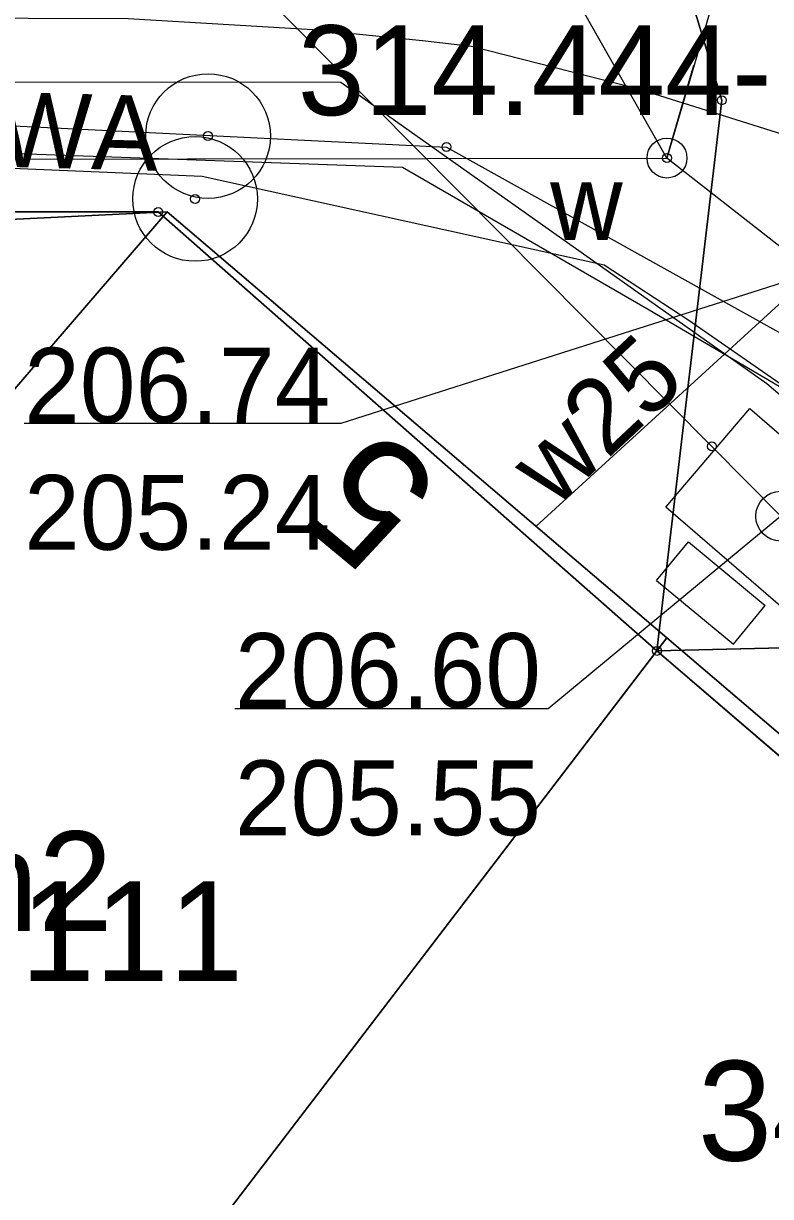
# Model space of a CAD drawing. Extents: x 6512400 to 6513200, y 6022500 to 6022750.
# Drawn here: x 6512795.61 to 6512803.1, y 6022664.87 to 6022676.63 of the extents above; entities that cross this region are included whole.
import ezdxf

# ---------------------------------------------------------------- set-up
doc = ezdxf.new("R2010")
doc.units = 0
for name, color, linetype in [('121-Punkt osnowy szczegółowej', 7, 'Continuous'), ('121-Punkt osnowy szczegółowej-Atr103', 7, 'Continuous'), ('203-punkt graniczny', 7, 'Continuous'), ('211-numer działki ewidencyjnej', 7, 'Continuous'), ('216-obręb ewidencyjny', 7, 'Continuous'), ('217-kontur klasyfikacyjny', 7, 'Continuous'), ('218-kontur użytku gruntowego', 7, 'Continuous'), ('219-działka ewidencyjna', 7, 'Continuous'), ('238-Punkt adresowy budynku', 7, 'Continuous'), ('312-budynek ewidencyjny', 7, 'Continuous'), ('312-oznaczenie budynku ewidencyjnego', 7, 'Continuous'), ('312-oznaczenie budynku ewidencyjnego-Atr117', 7, 'Continuous'), ('320-blok - kondygnacja nadziemna', 7, 'Continuous'), ('chodnik (powierzchnia)', 7, 'Continuous'), ('inna obudowa przewodu - sieć telekomunikacyjna (linia)', 7, 'Continuous'), ('inna obudowa przewodu - sieć wodociągowa (linia)', 7, 'Continuous'), ('komora podziemna - przewód telekomunikacyjny (powierzchnia)', 7, 'Continuous'), ('krawężnik (linia)', 7, 'Continuous'), ('przewód elektroenergetyczny (linia)', 7, 'Continuous'), ('przewód elektroenergetyczny (linia)-Atr1', 7, 'Continuous'), ('przewód telekomunikacyjny (linia)', 7, 'Continuous'), ('przewód wodociągowy (linia)', 7, 'Continuous'), ('przewód wodociągowy (linia)-Atr1', 7, 'Continuous'), ('punkt o określonej wysokości (sieć telekomunikacyjna)', 7, 'Continuous'), ('punkt o określonej wysokości (sieć telekomunikacyjna)-Atr2', 7, 'Continuous'), ('punkt o określonej wysokości (sieć telekomunikacyjna)-Atr3', 7, 'Continuous'), ('punkt o określonej wysokości (sieć wodociągowa)', 7, 'Continuous'), ('punkt o określonej wysokości (sieć wodociągowa)-Atr2', 7, 'Continuous'), ('punkt o określonej wysokości (sieć wodociągowa)-Atr3', 7, 'Continuous'), ('szafa telekomunikacyjna (punkt)', 7, 'Continuous'), ('właz okrągły - siec telekomunikacyjna (punkt)', 7, 'Continuous'), ('zasuwa - siec wodociągowa (punkt)', 7, 'Continuous'), ('zasuwa - siec wodociągowa (punkt)-Atr17', 7, 'Continuous')]:
    doc.layers.add(name, color=color, linetype=linetype)

# ---------------------------------------------------------------- blocks, each defined once
blk = doc.blocks.new('203')
blk.add_circle((0, 0), 0.045)
blk = doc.blocks.new('US17')
for p, q in [((-0.5, -0.25), (-0.5, 0.25)), ((-0.5, 0.25), (0.5, 0.25)), ((0.5, -0.25), (0.5, 0.25)), ((-0.5, -0.25), (0.5, -0.25))]:
    blk.add_line(p, q)
blk = doc.blocks.new('US22')
blk.add_circle((0, 0), 0.25)
blk = doc.blocks.new('PW01')
blk.add_circle((0, 0), 0.045)
blk = doc.blocks.new('US25')
blk.add_circle((0, 0), 0.2)
blk = doc.blocks.new('121')
for radius in [0.625, 0.045]:
    blk.add_circle((0, 0), radius)

msp = doc.modelspace()

# ---------------------------------------------------------------- linework, layer by layer
at = {"layer": '216-obręb ewidencyjny'}
for points in [[(6512688.62, 6022674.91), (6512702.58, 6022674.18), (6512725.78, 6022672.95), (6512730.35, 6022672.71), (6512735.76, 6022672.94), (6512745.51, 6022673.33), (6512754.87, 6022673.72), (6512768.24, 6022674.27), (6512785.56, 6022674.74), (6512790.49, 6022674.74), (6512796.96, 6022674.74), (6512801.96, 6022670.34), (6512828.67, 6022670.98), (6512833.61, 6022675.02), (6512836.69, 6022675.17), (6512851.94, 6022675.93)], [(6512836.687, 6022675.173), (6512833.61, 6022675.02), (6512828.67, 6022670.98), (6512801.96, 6022670.34), (6512810.18, 6022663.28), (6512825.37, 6022649.66), (6512838.47, 6022634.29), (6512852.25, 6022608.25), (6512853.17, 6022604.51), (6512855.78, 6022583.95), (6512858.85, 6022571.74), (6512828.23, 6022562.62), (6512818.47, 6022559.72), (6512824.714, 6022553.406)], [(6512780.7, 6022581.02), (6512806.2, 6022572.11), (6512806.62, 6022563.51), (6512811.41, 6022558.95), (6512818.47, 6022559.72), (6512828.23, 6022562.62), (6512858.85, 6022571.74), (6512855.78, 6022583.95), (6512853.17, 6022604.51), (6512852.25, 6022608.25), (6512838.47, 6022634.29), (6512825.37, 6022649.66), (6512810.18, 6022663.28), (6512801.96, 6022670.34), (6512796.96, 6022674.74), (6512790.49, 6022674.74), (6512785.56, 6022674.74), (6512768.24, 6022674.27)]]:
    msp.add_lwpolyline(points, dxfattribs=at)
at = {"layer": '217-kontur klasyfikacyjny'}
for points in [[(6512801.96, 6022670.34), (6512795.54, 6022661.95)], [(6512810.18, 6022663.28), (6512801.96, 6022670.34)]]:
    msp.add_lwpolyline(points, dxfattribs=at)
at = {"layer": '218-kontur użytku gruntowego'}
for points in [[(6512798.3, 6022690.12), (6512802.61, 6022675.86)], [(6512802.61, 6022675.86), (6512798.3, 6022690.12)], [(6512802.61, 6022675.86), (6512801.96, 6022670.34)], [(6512801.96, 6022670.34), (6512802.61, 6022675.86)], [(6512796.96, 6022674.74), (6512785.56, 6022674.74)], [(6512785.56, 6022674.74), (6512796.96, 6022674.74)], [(6512801.96, 6022670.34), (6512796.96, 6022674.74)], [(6512796.96, 6022674.74), (6512801.96, 6022670.34)], [(6512801.96, 6022670.34), (6512828.67, 6022670.98)], [(6512828.67, 6022670.98), (6512801.96, 6022670.34)], [(6512801.96, 6022670.34), (6512795.54, 6022661.95)], [(6512795.54, 6022661.95), (6512801.96, 6022670.34)], [(6512810.18, 6022663.28), (6512801.96, 6022670.34)], [(6512801.96, 6022670.34), (6512810.18, 6022663.28)]]:
    msp.add_lwpolyline(points, dxfattribs=at)
at = {"layer": '219-działka ewidencyjna'}
for points in [[(6512802.61, 6022675.86), (6512798.3, 6022690.12)], [(6512802.61, 6022675.86), (6512801.96, 6022670.34)], [(6512796.96, 6022674.74), (6512790.49, 6022674.74)], [(6512801.96, 6022670.34), (6512796.96, 6022674.74)], [(6512828.67, 6022670.98), (6512801.96, 6022670.34)], [(6512801.96, 6022670.34), (6512795.54, 6022661.95)], [(6512801.96, 6022670.34), (6512810.18, 6022663.28)]]:
    msp.add_lwpolyline(points, dxfattribs=at)
at = {"layer": '312-budynek ewidencyjny'}
for points in [[(6512785.32, 6022674.17), (6512797.05, 6022674.74)], [(6512789.92, 6022666.46), (6512797.05, 6022674.74)], [(6512797.05, 6022674.74), (6512789.92, 6022666.46)], [(6512797.05, 6022674.74), (6512802.06, 6022670.47)], [(6512795.54, 6022661.95), (6512802.06, 6022670.47)], [(6512802.06, 6022670.47), (6512795.54, 6022661.95)], [(6512802.06, 6022670.47), (6512810.3, 6022663.44)]]:
    msp.add_lwpolyline(points, dxfattribs=at)
at = {"layer": '320-blok - kondygnacja nadziemna'}
msp.add_lwpolyline([(6512789.92, 6022666.46), (6512797.05, 6022674.74), (6512785.32, 6022674.17), (6512786.09, 6022669.52)], close=True, dxfattribs=at)
at = {"layer": 'chodnik (powierzchnia)'}
for points in [[(6512768.21, 6022674.06), (6512768.55, 6022674.06), (6512785.32, 6022674.17), (6512797.05, 6022674.74)], [(6512845.61, 6022610.5), (6512844.69, 6022613.44), (6512844.06, 6022613.28), (6512843.41, 6022615.01), (6512844.01, 6022615.23), (6512838.87, 6022629.83), (6512839.52, 6022630.32), (6512838.94, 6022631.84), (6512838.15, 6022631.88), (6512837.86, 6022632.79), (6512838.13, 6022633.96), (6512826.89, 6022646.81), (6512825.11, 6022648.85), (6512824.32, 6022649.76), (6512820.29, 6022654.03), (6512817.62, 6022656.88), (6512816.1, 6022658.5), (6512810.3, 6022663.44), (6512802.06, 6022670.47), (6512797.05, 6022674.74)]]:
    msp.add_lwpolyline(points, dxfattribs=at)
at = {"layer": 'inna obudowa przewodu - sieć telekomunikacyjna (linia)'}
msp.add_lwpolyline([(6512802.54, 6022672.36), (6512802.51, 6022672.39), (6512787.26, 6022687.76), (6512787.22, 6022687.8)], dxfattribs=at)
at = {"layer": 'inna obudowa przewodu - sieć wodociągowa (linia)'}
msp.add_lwpolyline([(6512787.61, 6022675.99), (6512796.6, 6022675.55)], dxfattribs=at)
at = {"layer": 'komora podziemna - przewód telekomunikacyjny (powierzchnia)'}
msp.add_lwpolyline([(6512804.22, 6022671.62), (6512803.37, 6022670.64), (6512802.05, 6022671.78), (6512802.89, 6022672.77)], close=True, dxfattribs=at)
at = {"layer": 'krawężnik (linia)'}
for points in [[(6512769.23, 6022676.77), (6512772.62, 6022676.76), (6512796.66, 6022676.68), (6512798.51, 6022676.57), (6512799.61, 6022676.46)], [(6512799.61, 6022676.46), (6512800.1, 6022676.4), (6512801.75, 6022675.98), (6512803.57, 6022675.41), (6512805.87, 6022674.59), (6512808.65, 6022673.67), (6512810.69, 6022673.23), (6512812.18, 6022673.12), (6512821.17, 6022672.6), (6512827.66, 6022672.22)]]:
    msp.add_lwpolyline(points, dxfattribs=at)
at = {"layer": 'przewód elektroenergetyczny (linia)'}
for points in [[(6512763.38, 6022676.06), (6512798.79, 6022676.04), (6512803.06, 6022673.02), (6512807.84, 6022668.96), (6512815.24, 6022662.53), (6512819.98, 6022657.77), (6512831.6, 6022645.79), (6512834.59, 6022642.25), (6512837.06, 6022638.75), (6512840.02, 6022634.13), (6512842.26, 6022630.04), (6512846.03, 6022621.35), (6512846.58, 6022618.9), (6512847.6, 6022616.23), (6512852.12, 6022605.09), (6512853.39, 6022601.13), (6512855.57, 6022592.48), (6512858.1, 6022582.86), (6512868.09, 6022584.49), (6512870.03, 6022584.23), (6512871.36, 6022584.34), (6512875.65, 6022585.56), (6512879.74, 6022586.61), (6512881.754, 6022587.357)], [(6512776, 6022676.02), (6512799.41, 6022675.19), (6512801.88, 6022673.76), (6512804.18, 6022672.41), (6512807.52, 6022669.86), (6512808.59, 6022669.6), (6512810.5, 6022669.85), (6512831.73, 6022668.71)], [(6512787.87, 6022675.5), (6512797.4, 6022675.1), (6512801.43, 6022674.21), (6512802.27, 6022673.66)], [(6512802.27, 6022673.66), (6512807.42, 6022670.09), (6512811.38, 6022666.87), (6512814.66, 6022663.43), (6512826.4, 6022651.65), (6512827.82, 6022650.09), (6512834.03, 6022642.46), (6512842.84, 6022631.19), (6512844.67, 6022626.95), (6512847.57, 6022619.87), (6512849.81, 6022612.67), (6512853.56, 6022600.08), (6512856.46, 6022588.83), (6512861.26, 6022569.82), (6512861.768, 6022567.654)]]:
    msp.add_lwpolyline(points, dxfattribs=at)
at = {"layer": 'przewód telekomunikacyjny (linia)'}
msp.add_lwpolyline([(6512803.2, 6022671.69), (6512802.51, 6022672.39), (6512787.26, 6022687.76), (6512786.53, 6022688.5)], dxfattribs=at)
at = {"layer": 'przewód wodociągowy (linia)'}
for points in [[(6512803.06, 6022678.69), (6512802.06, 6022675.28)], [(6512776.98, 6022676.45), (6512777.41, 6022676.47), (6512777.83, 6022676.47), (6512787.32, 6022676), (6512787.61, 6022675.99), (6512796.6, 6022675.55), (6512799.85, 6022675.39), (6512814.29, 6022667.35), (6512815.22, 6022667.12), (6512815.2, 6022666.73), (6512814.74, 6022665.5)], [(6512803.53, 6022674.13), (6512802.06, 6022675.28), (6512802.33, 6022676.21)], [(6512787.64, 6022675.26), (6512802.06, 6022675.28)], [(6512803.53, 6022674.13), (6512800.75, 6022671.59)]]:
    msp.add_lwpolyline(points, dxfattribs=at)
at = {"layer": 'punkt o określonej wysokości (sieć telekomunikacyjna)-Atr2'}
msp.add_lwpolyline([(6512803.2, 6022671.69), (6512800.87, 6022669.76), (6512797.729, 6022669.76)], dxfattribs=at)
at = {"layer": 'punkt o określonej wysokości (sieć wodociągowa)-Atr2'}
for points in [[(6512802.06, 6022675.28), (6512799.9, 6022679.08), (6512796.759, 6022679.08)], [(6512803.53, 6022674.13), (6512798.79, 6022672.62), (6512795.617, 6022672.62)]]:
    msp.add_lwpolyline(points, dxfattribs=at)

# ---------------------------------------------------------------- block references
at = {"layer": '121-Punkt osnowy szczegółowej'}
for p in [(6512797.46, 6022675.5), (6512797.33, 6022674.87)]:
    msp.add_blockref('121', p, dxfattribs=at)
at = {"layer": '203-punkt graniczny'}
for p in [(6512802.61, 6022675.86), (6512796.96, 6022674.74), (6512801.96, 6022670.34)]:
    msp.add_blockref('203', p, dxfattribs=at)
at = {"layer": 'punkt o określonej wysokości (sieć telekomunikacyjna)', "rotation": -44.435}
msp.add_blockref('PW01', (6512802.51, 6022672.39), dxfattribs=at)
at = {"layer": 'punkt o określonej wysokości (sieć wodociągowa)'}
msp.add_blockref('PW01', (6512799.85, 6022675.39), dxfattribs=at)
at = {"layer": 'punkt o określonej wysokości (sieć wodociągowa)', "rotation": 74.539}
msp.add_blockref('PW01', (6512802.06, 6022675.28), dxfattribs=at)
at = {"layer": 'szafa telekomunikacyjna (punkt)', "rotation": -39.63600000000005}
msp.add_blockref('US17', (6512802.5, 6022670.92), dxfattribs=at)
at = {"layer": 'właz okrągły - siec telekomunikacyjna (punkt)', "rotation": -43.02}
msp.add_blockref('US22', (6512803.2, 6022671.69), dxfattribs=at)
at = {"layer": 'zasuwa - siec wodociągowa (punkt)', "rotation": 74.539}
msp.add_blockref('US25', (6512802.06, 6022675.28), dxfattribs=at)

# ---------------------------------------------------------------- texts
at = {"layer": '121-Punkt osnowy szczegółowej-Atr103'}
msp.add_text('314.444-113106', height=0.9, dxfattribs=at).set_placement((6512798.36, 6022675.71))
at = {"layer": '211-numer działki ewidencyjnej'}
msp.add_text('34/1', height=1, dxfattribs=at).set_placement((6512802.37, 6022665.23))
at = {"layer": '238-Punkt adresowy budynku'}
msp.add_text('5', height=1.25, rotation=140.363, dxfattribs=at).set_placement((6512799.84, 6022672.03))
at = {"layer": '312-oznaczenie budynku ewidencyjnego'}
msp.add_text('111', height=1, dxfattribs=at).set_placement((6512795.58, 6022667.03))
at = {"layer": '312-oznaczenie budynku ewidencyjnego-Atr117'}
msp.add_text('m2', height=1, dxfattribs=at).set_placement((6512794.645, 6022667.53))
at = {"layer": 'przewód elektroenergetyczny (linia)-Atr1'}
msp.add_text('eWA', height=0.75, rotation=358.456, dxfattribs=at).set_placement((6512794.78, 6022675.21))
at = {"layer": 'przewód wodociągowy (linia)-Atr1'}
msp.add_text('w25', height=0.75, rotation=43.133, dxfattribs=at).set_placement((6512800.93, 6022671.76))
at = {"layer": 'punkt o określonej wysokości (sieć telekomunikacyjna)-Atr2'}
msp.add_text('206.60', height=0.75, dxfattribs=at).set_placement((6512797.729, 6022669.768))
at = {"layer": 'punkt o określonej wysokości (sieć telekomunikacyjna)-Atr3'}
msp.add_text('205.55', height=0.75, dxfattribs=at).set_placement((6512797.729, 6022668.492))
at = {"layer": 'punkt o określonej wysokości (sieć wodociągowa)-Atr2'}
msp.add_text('206.74', height=0.75, dxfattribs=at).set_placement((6512795.617, 6022672.628))
at = {"layer": 'punkt o określonej wysokości (sieć wodociągowa)-Atr3'}
msp.add_text('205.24', height=0.75, dxfattribs=at).set_placement((6512795.617, 6022671.353))
at = {"layer": 'zasuwa - siec wodociągowa (punkt)-Atr17'}
msp.add_text('w', height=0.75, dxfattribs=at).set_placement((6512800.89, 6022674.46))

doc.saveas('drawing.dxf')
